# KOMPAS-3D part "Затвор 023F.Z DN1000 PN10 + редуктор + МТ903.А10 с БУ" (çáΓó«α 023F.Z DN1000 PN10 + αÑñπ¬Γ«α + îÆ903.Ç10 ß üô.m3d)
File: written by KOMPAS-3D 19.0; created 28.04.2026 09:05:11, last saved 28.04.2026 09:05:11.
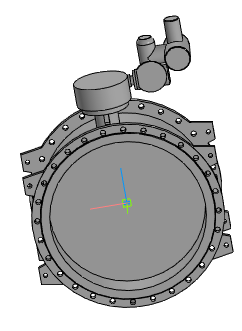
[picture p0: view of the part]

Document properties: Полное имя файла: ..\..\Затвор 023F.Z DN400-DN1600 + редуктор + МТ903\Затвор 023F.Z DN1000 PN10 + редуктор + МТ903.А10 с БУ.a3d

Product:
- Part/product: Затвор 023F.Z DN1000 PN10 + редуктор + МТ903.А10 с БУ
    Масса: 1439.81

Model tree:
1. Операция без истории:1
